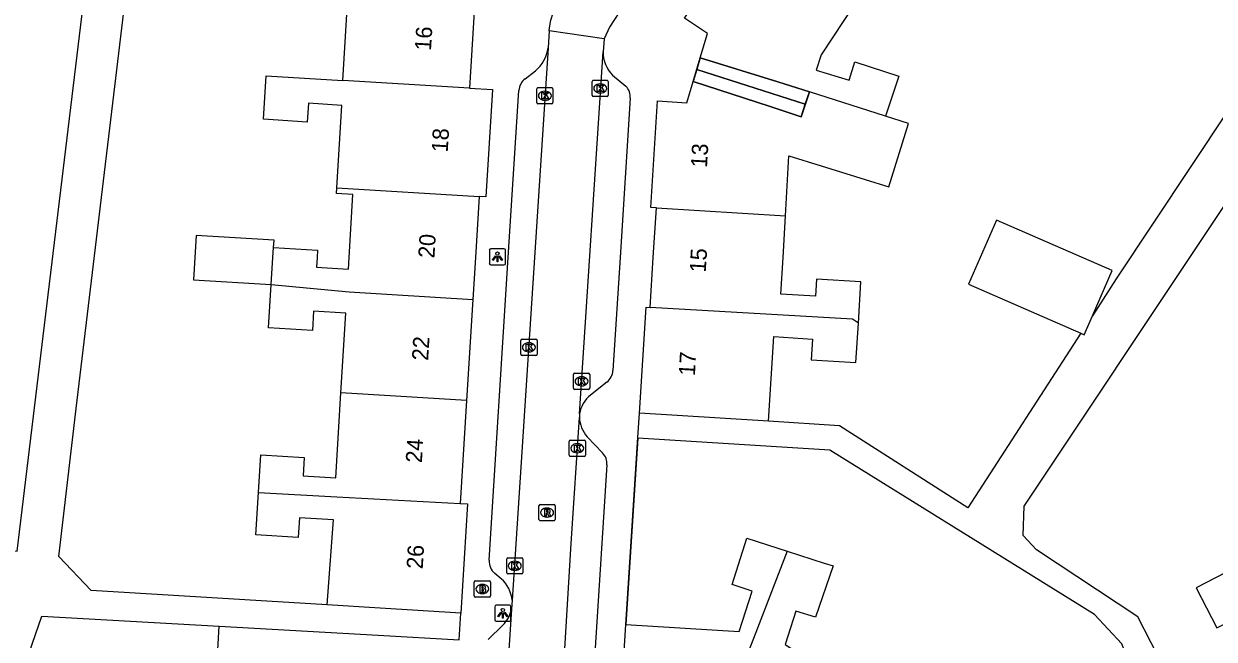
# Model space of a CAD drawing. Extents: x 159280 to 160375, y 384531 to 385872.
# Drawn here: x 160014.7 to 160088.1, y 384726.4 to 384764.4 of the extents above; entities that cross this region are included whole.
import ezdxf

# ---------------------------------------------------------------- set-up
doc = ezdxf.new("R2010")
doc.units = 0
for name, color, linetype in [('IMGEO_Brandkraan', 7, 'Continuous'), ('IMGEO_Kolk', 7, 'Continuous'), ('IMGEO_Lichtpunt', 7, 'Continuous'), ('IMGEO_Muur', 7, 'Continuous'), ('IMGEO_Pand', 7, 'Continuous'), ('IMGEO_Pand_nummerreeks', 7, 'Continuous'), ('IMGEO_Pand_overbouw', 7, 'Continuous'), ('IMGEO_Rijbaan_lokaal_open', 7, 'Continuous'), ('IMGEO_Rioolput', 7, 'Continuous'), ('IMGEO_Voetpad_open', 7, 'Continuous')]:
    doc.layers.add(name, color=color, linetype=linetype)

msp = doc.modelspace()

# ---------------------------------------------------------------- linework, layer by layer
at = {"layer": 'IMGEO_Brandkraan'}
for p, q in [((160042.486, 384729.118), (160042.486, 384729.97)), ((160042.561, 384730.044), (160043.413, 384730.044)), ((160042.974, 384729.824), (160042.999, 384729.824)), ((160043.487, 384729.97), (160043.487, 384729.118)), ((160043.413, 384729.044), (160042.561, 384729.044)), ((160042.997, 384729.264), (160042.972, 384729.264))]:
    msp.add_line(p, q, dxfattribs=at)
for points in [[(160042.486, 384729.118), (160042.486, 384729.97)], [(160042.561, 384730.044), (160043.413, 384730.044)], [(160042.834, 384729.744), (160042.834, 384729.344), (160043.047, 384729.344)], [(160043.065, 384729.744), (160042.834, 384729.744)], [(160043.013, 384729.663), (160042.959, 384729.663), (160042.959, 384729.587)], [(160042.959, 384729.587), (160043.012, 384729.587)], [(160043.021, 384729.511), (160042.959, 384729.511), (160042.959, 384729.43)], [(160042.959, 384729.43), (160043.021, 384729.43)], [(160043.487, 384729.97), (160043.487, 384729.118)], [(160043.413, 384729.044), (160042.561, 384729.044)]]:
    msp.add_lwpolyline(points, dxfattribs=at)
for centre, radius, start, end in [((160042.563, 384729.968), 0.0765, 91.55205, 178.44795), ((160042.563, 384729.968), 0.0765, 91.55205, 178.44795), ((160043.014, 384729.625), 0.0379, 267.82845, 90.93552), ((160043.022, 384729.47), 0.0404, 269.87594, 90.50774), ((160043.069, 384729.599), 0.145, 59.4692, 91.53667), ((160043.094, 384729.646), 0.0922, 285.51372, 58.15012), ((160043.099, 384729.454), 0.105, 301.31148, 78.98903), ((160043.411, 384729.968), 0.0765, 1.55205, 88.44795), ((160043.411, 384729.968), 0.0765, 1.55205, 88.44795), ((160042.563, 384729.12), 0.0765, 181.55205, 268.44795), ((160042.563, 384729.12), 0.0765, 181.55205, 268.44795), ((160043.053, 384729.595), 0.251, 268.66757, 293.53466), ((160043.411, 384729.12), 0.0765, 271.55205, 358.44795), ((160043.411, 384729.12), 0.0765, 271.55205, 358.44795)]:
    msp.add_arc(centre, radius, start, end, dxfattribs=at)
for centre, major_axis, ratio, start_param, end_param in [((160042.973, 384729.544), (-0.387, 0.002), 0.722429, 4.712389, 7.853982), ((160042.998, 384729.544), (-0.39, 0.002), 0.717154, 1.570796, 4.712389)]:
    msp.add_ellipse(centre, major_axis=major_axis, ratio=ratio, start_param=start_param, end_param=end_param, dxfattribs=at)
at = {"layer": 'IMGEO_Kolk'}
for p, q in [((160046.34, 384759.554), (160046.34, 384760.406)), ((160046.415, 384760.48), (160047.267, 384760.48)), ((160046.828, 384760.26), (160046.853, 384760.26)), ((160047.341, 384760.406), (160047.341, 384759.554)), ((160049.754, 384760.006), (160049.754, 384760.858)), ((160049.829, 384760.932), (160050.681, 384760.932)), ((160050.242, 384760.712), (160050.267, 384760.712)), ((160050.755, 384760.858), (160050.755, 384760.006)), ((160046.851, 384759.7), (160046.826, 384759.7)), ((160050.681, 384759.932), (160049.829, 384759.932)), ((160050.265, 384760.152), (160050.24, 384760.152)), ((160047.267, 384759.48), (160046.415, 384759.48)), ((160045.359, 384744.032), (160045.359, 384744.884)), ((160045.434, 384744.958), (160046.286, 384744.958)), ((160046.36, 384744.884), (160046.36, 384744.032)), ((160045.87, 384744.178), (160045.845, 384744.178)), ((160045.847, 384744.738), (160045.872, 384744.738)), ((160046.286, 384743.958), (160045.434, 384743.958)), ((160048.605, 384741.934), (160048.605, 384742.786)), ((160048.68, 384742.86), (160049.532, 384742.86)), ((160049.093, 384742.64), (160049.118, 384742.64)), ((160049.606, 384742.786), (160049.606, 384741.934)), ((160049.116, 384742.08), (160049.091, 384742.08)), ((160049.532, 384741.86), (160048.68, 384741.86)), ((160048.343, 384737.803), (160048.343, 384738.655)), ((160048.418, 384738.729), (160049.27, 384738.729)), ((160048.831, 384738.509), (160048.856, 384738.509)), ((160049.344, 384738.655), (160049.344, 384737.803)), ((160049.27, 384737.729), (160048.418, 384737.729)), ((160048.854, 384737.949), (160048.829, 384737.949)), ((160044.487, 384730.55), (160044.487, 384731.402)), ((160044.562, 384731.476), (160045.414, 384731.476)), ((160044.975, 384731.256), (160045, 384731.256)), ((160045.488, 384731.402), (160045.488, 384730.55)), ((160045.414, 384730.476), (160044.562, 384730.476)), ((160044.998, 384730.696), (160044.973, 384730.696))]:
    msp.add_line(p, q, dxfattribs=at)
for points in [[(160046.34, 384759.554), (160046.34, 384760.406)], [(160046.415, 384760.48), (160047.267, 384760.48)], [(160047.341, 384760.406), (160047.341, 384759.554)], [(160049.754, 384760.006), (160049.754, 384760.858)], [(160049.829, 384760.932), (160050.681, 384760.932)], [(160050.075, 384760.632), (160050.198, 384760.632), (160050.198, 384760.481), (160050.328, 384760.632), (160050.492, 384760.632), (160050.346, 384760.481), (160050.499, 384760.232), (160050.347, 384760.232), (160050.262, 384760.396), (160050.198, 384760.329), (160050.198, 384760.232), (160050.075, 384760.232), (160050.075, 384760.632)], [(160050.755, 384760.858), (160050.755, 384760.006)], [(160046.661, 384760.18), (160046.784, 384760.18), (160046.784, 384760.029), (160046.914, 384760.18), (160047.078, 384760.18), (160046.932, 384760.029), (160047.085, 384759.78), (160046.933, 384759.78), (160046.848, 384759.944), (160046.784, 384759.877), (160046.784, 384759.78), (160046.661, 384759.78), (160046.661, 384760.18)], [(160050.681, 384759.932), (160049.829, 384759.932)], [(160047.267, 384759.48), (160046.415, 384759.48)], [(160045.359, 384744.032), (160045.359, 384744.884)], [(160045.434, 384744.958), (160046.286, 384744.958)], [(160046.36, 384744.884), (160046.36, 384744.032)], [(160045.68, 384744.658), (160045.803, 384744.658), (160045.803, 384744.507), (160045.933, 384744.658), (160046.097, 384744.658), (160045.951, 384744.507), (160046.104, 384744.258), (160045.952, 384744.258), (160045.867, 384744.422), (160045.803, 384744.355), (160045.803, 384744.258), (160045.68, 384744.258), (160045.68, 384744.658)], [(160046.286, 384743.958), (160045.434, 384743.958)], [(160048.605, 384741.934), (160048.605, 384742.786)], [(160048.68, 384742.86), (160049.532, 384742.86)], [(160049.606, 384742.786), (160049.606, 384741.934)], [(160048.926, 384742.56), (160049.049, 384742.56), (160049.049, 384742.409), (160049.179, 384742.56), (160049.343, 384742.56), (160049.197, 384742.409), (160049.35, 384742.16), (160049.198, 384742.16), (160049.113, 384742.324), (160049.049, 384742.257), (160049.049, 384742.16), (160048.926, 384742.16), (160048.926, 384742.56)], [(160049.532, 384741.86), (160048.68, 384741.86)], [(160048.343, 384737.803), (160048.343, 384738.655)], [(160048.418, 384738.729), (160049.27, 384738.729)], [(160048.664, 384738.429), (160048.787, 384738.429), (160048.787, 384738.278), (160048.917, 384738.429), (160049.081, 384738.429), (160048.935, 384738.278), (160049.088, 384738.029), (160048.936, 384738.029), (160048.851, 384738.193), (160048.787, 384738.126), (160048.787, 384738.029), (160048.664, 384738.029), (160048.664, 384738.429)], [(160049.344, 384738.655), (160049.344, 384737.803)], [(160049.27, 384737.729), (160048.418, 384737.729)], [(160044.487, 384730.55), (160044.487, 384731.402)], [(160044.562, 384731.476), (160045.414, 384731.476)], [(160044.808, 384731.176), (160044.931, 384731.176), (160044.931, 384731.025), (160045.061, 384731.176), (160045.225, 384731.176), (160045.079, 384731.025), (160045.232, 384730.776), (160045.08, 384730.776), (160044.995, 384730.94), (160044.931, 384730.873), (160044.931, 384730.776), (160044.808, 384730.776), (160044.808, 384731.176)], [(160045.488, 384731.402), (160045.488, 384730.55)], [(160045.414, 384730.476), (160044.562, 384730.476)]]:
    msp.add_lwpolyline(points, dxfattribs=at)
for centre, start, end in [((160046.417, 384760.404), 91.55205, 178.44795), ((160046.417, 384760.404), 91.55205, 178.44795), ((160047.265, 384760.404), 1.55205, 88.44795), ((160047.265, 384760.404), 1.55205, 88.44795), ((160049.831, 384760.856), 91.55205, 178.44795), ((160049.831, 384760.856), 91.55205, 178.44795), ((160050.679, 384760.856), 1.55205, 88.44795), ((160050.679, 384760.856), 1.55205, 88.44795), ((160046.417, 384759.556), 181.55205, 268.44795), ((160046.417, 384759.556), 181.55205, 268.44795), ((160047.265, 384759.556), 271.55205, 358.44795), ((160047.265, 384759.556), 271.55205, 358.44795), ((160049.831, 384760.008), 181.55205, 268.44795), ((160049.831, 384760.008), 181.55205, 268.44795), ((160050.679, 384760.008), 271.55205, 358.44795), ((160050.679, 384760.008), 271.55205, 358.44795), ((160045.436, 384744.882), 91.55205, 178.44795), ((160045.436, 384744.882), 91.55205, 178.44795), ((160046.284, 384744.882), 1.55205, 88.44795), ((160046.284, 384744.882), 1.55205, 88.44795), ((160045.436, 384744.034), 181.55205, 268.44795), ((160045.436, 384744.034), 181.55205, 268.44795), ((160046.284, 384744.034), 271.55205, 358.44795), ((160046.284, 384744.034), 271.55205, 358.44795), ((160048.682, 384742.784), 91.55205, 178.44795), ((160048.682, 384742.784), 91.55205, 178.44795), ((160049.53, 384742.784), 1.55205, 88.44795), ((160049.53, 384742.784), 1.55205, 88.44795), ((160048.682, 384741.936), 181.55205, 268.44795), ((160048.682, 384741.936), 181.55205, 268.44795), ((160049.53, 384741.936), 271.55205, 358.44795), ((160049.53, 384741.936), 271.55205, 358.44795), ((160048.42, 384738.653), 91.55205, 178.44795), ((160048.42, 384738.653), 91.55205, 178.44795), ((160049.268, 384738.653), 1.55205, 88.44795), ((160049.268, 384738.653), 1.55205, 88.44795), ((160048.42, 384737.805), 181.55205, 268.44795), ((160048.42, 384737.805), 181.55205, 268.44795), ((160049.268, 384737.805), 271.55205, 358.44795), ((160049.268, 384737.805), 271.55205, 358.44795), ((160044.564, 384731.4), 91.55205, 178.44795), ((160044.564, 384731.4), 91.55205, 178.44795), ((160045.412, 384731.4), 1.55205, 88.44795), ((160045.412, 384731.4), 1.55205, 88.44795), ((160044.564, 384730.552), 181.55205, 268.44795), ((160044.564, 384730.552), 181.55205, 268.44795), ((160045.412, 384730.552), 271.55205, 358.44795), ((160045.412, 384730.552), 271.55205, 358.44795)]:
    msp.add_arc(centre, 0.0765, start, end, dxfattribs=at)
for centre, major_axis, ratio, start_param, end_param in [((160046.827, 384759.98), (-0.387, 0.002), 0.722429, 4.712389, 7.853982), ((160046.852, 384759.98), (-0.39, 0.002), 0.717154, 1.570796, 4.712389), ((160050.241, 384760.432), (-0.387, 0.002), 0.722429, 4.712389, 7.853982), ((160050.266, 384760.432), (-0.39, 0.002), 0.717154, 1.570796, 4.712389), ((160045.846, 384744.458), (-0.387, 0.002), 0.722429, 4.712389, 7.853982), ((160045.871, 384744.458), (-0.39, 0.002), 0.717154, 1.570796, 4.712389), ((160049.092, 384742.36), (-0.387, 0.002), 0.722429, 4.712389, 7.853982), ((160049.117, 384742.36), (-0.39, 0.002), 0.717154, 1.570796, 4.712389), ((160048.83, 384738.229), (-0.387, 0.002), 0.722429, 4.712389, 7.853982), ((160048.855, 384738.229), (-0.39, 0.002), 0.717154, 1.570796, 4.712389), ((160044.974, 384730.976), (-0.387, 0.002), 0.722429, 4.712389, 7.853982), ((160044.999, 384730.976), (-0.39, 0.002), 0.717154, 1.570796, 4.712389)]:
    msp.add_ellipse(centre, major_axis=major_axis, ratio=ratio, start_param=start_param, end_param=end_param, dxfattribs=at)
at = {"layer": 'IMGEO_Lichtpunt'}
for p, q in [((160043.418, 384750.444), (160043.418, 384749.637)), ((160043.418, 384750.444), (160043.418, 384749.637)), ((160044.32, 384750.539), (160043.512, 384750.539)), ((160044.32, 384750.539), (160043.512, 384750.539)), ((160044.414, 384749.637), (160044.414, 384750.444)), ((160044.414, 384749.637), (160044.414, 384750.444)), ((160043.512, 384749.543), (160044.32, 384749.543)), ((160043.512, 384749.543), (160044.32, 384749.543)), ((160043.754, 384728.45), (160043.754, 384727.643)), ((160043.754, 384728.45), (160043.754, 384727.643)), ((160044.656, 384728.545), (160043.848, 384728.545)), ((160044.656, 384728.545), (160043.848, 384728.545)), ((160044.75, 384727.643), (160044.75, 384728.45)), ((160044.75, 384727.643), (160044.75, 384728.45)), ((160043.848, 384727.549), (160044.656, 384727.549)), ((160043.848, 384727.549), (160044.656, 384727.549))]:
    msp.add_line(p, q, dxfattribs=at)
for points in [[(160043.792, 384750.108), (160043.831, 384750.08), (160043.643, 384749.818), (160043.605, 384749.845), (160043.792, 384750.108)], [(160043.894, 384750.06), (160043.941, 384750.06), (160043.941, 384749.738), (160043.894, 384749.738), (160043.894, 384750.06)], [(160044.004, 384750.08), (160044.042, 384750.107), (160044.229, 384749.845), (160044.19, 384749.817), (160044.004, 384750.08)], [(160044.128, 384728.114), (160044.167, 384728.086), (160043.979, 384727.824), (160043.941, 384727.851), (160044.128, 384728.114)], [(160044.23, 384728.066), (160044.277, 384728.066), (160044.277, 384727.744), (160044.23, 384727.744), (160044.23, 384728.066)], [(160044.34, 384728.086), (160044.378, 384728.113), (160044.565, 384727.851), (160044.526, 384727.823), (160044.34, 384728.086)]]:
    msp.add_lwpolyline(points, dxfattribs=at)
for centre in [(160043.917, 384750.242), (160044.253, 384728.248)]:
    msp.add_circle(centre, 0.0994, dxfattribs=at)
for centre, start, end in [((160043.512, 384750.444), 90, 180), ((160043.512, 384750.444), 90, 180), ((160044.32, 384750.444), 0, 90), ((160044.32, 384750.444), 0, 90), ((160043.512, 384749.637), 180, 270), ((160043.512, 384749.637), 180, 270), ((160044.32, 384749.637), 270, 0), ((160044.32, 384749.637), 270, 360), ((160043.848, 384728.45), 90, 180), ((160043.848, 384728.45), 90, 180), ((160044.656, 384728.45), 0, 90), ((160044.656, 384728.45), 0, 90), ((160043.848, 384727.643), 180, 270), ((160043.848, 384727.643), 180, 270), ((160044.656, 384727.643), 270, 0), ((160044.656, 384727.643), 270, 360)]:
    msp.add_arc(centre, 0.0946, start, end, dxfattribs=at)
at = {"layer": 'IMGEO_Muur'}
msp.add_lwpolyline([(160051.838, 384727.361), (160052.578, 384738.89)], dxfattribs=at)
at = {"layer": 'IMGEO_Pand'}
for points in [[(160034.384, 384760.923), (160034.78, 384767.393), (160032.683, 384768.135), (160032.319, 384766.974), (160029.657, 384767.772), (160030.296, 384769.918)], [(160056.43, 384762.314), (160056.88, 384763.817), (160055.458, 384764.761), (160059.135, 384770.303), (160059.437, 384770.102)], [(160042.553, 384766.197), (160042.2, 384760.442)], [(160065.958, 384765.643), (160063.874, 384762.502), (160063.57, 384761.554), (160065.601, 384760.943), (160065.966, 384762.073), (160068.678, 384761.186), (160067.849, 384758.715)], [(160056.43, 384762.314), (160061.205, 384760.83), (160063.156, 384760.223)], [(160034.01, 384754.297), (160034.322, 384759.387), (160032.256, 384759.513), (160032.185, 384758.36), (160029.483, 384758.525), (160029.648, 384761.215), (160034.384, 384760.923)], [(160042.2, 384760.442), (160034.384, 384760.923)], [(160042.2, 384760.442), (160043.61, 384760.356), (160043.205, 384753.733), (160042.786, 384753.758)], [(160053.724, 384753.069), (160053.385, 384753.092), (160053.795, 384759.662), (160055.601, 384759.55), (160055.995, 384760.866)], [(160063.156, 384760.223), (160062.653, 384758.682), (160060.746, 384759.308), (160055.995, 384760.866)], [(160067.849, 384758.715), (160063.156, 384760.223)], [(160061.681, 384752.573), (160061.896, 384756.264), (160063.875, 384755.649), (160066.597, 384754.822), (160068.058, 384754.368), (160069.272, 384758.273), (160067.849, 384758.715)], [(160030.11, 384750.616), (160032.83, 384750.45), (160032.802, 384750), (160032.765, 384749.393), (160034.724, 384749.273), (160034.768, 384750), (160035.006, 384753.892), (160033.989, 384753.954), (160034.01, 384754.297)], [(160034.01, 384754.297), (160042.786, 384753.758)], [(160042.786, 384753.758), (160042.556, 384750), (160042.397, 384747.403)], [(160053.339, 384746.908), (160053.532, 384750), (160053.724, 384753.069)], [(160053.724, 384753.069), (160061.681, 384752.573)], [(160066.177, 384745.957), (160066.335, 384748.489), (160063.591, 384748.66), (160063.526, 384747.608), (160061.399, 384747.741), (160061.531, 384750), (160061.681, 384752.573)], [(160080.608, 384746.402), (160081.826, 384749.194), (160074.698, 384752.305), (160072.971, 384748.347), (160079.906, 384745.32)], [(160030.11, 384750.616), (160030.137, 384751.062), (160025.344, 384751.355), (160025.177, 384748.624), (160029.97, 384748.331)], [(160029.97, 384748.331), (160030.072, 384750), (160030.11, 384750.616)], [(160034.267, 384741.64), (160034.569, 384746.57), (160032.582, 384746.692), (160032.509, 384745.485), (160029.806, 384745.651), (160029.97, 384748.331)], [(160029.97, 384748.331), (160034.763, 384747.871), (160042.397, 384747.403)], [(160042.397, 384747.403), (160042.015, 384741.166)], [(160052.673, 384740.386), (160053.08, 384746.924), (160053.339, 384746.908)], [(160066.177, 384745.957), (160065.821, 384746.19), (160053.339, 384746.908)], [(160079.906, 384745.32), (160080.099, 384745.236), (160080.608, 384746.402)], [(160060.631, 384739.89), (160060.957, 384745.119), (160063.352, 384744.969), (160063.271, 384743.683), (160066.025, 384743.512), (160066.177, 384745.957)], [(160029.182, 384735.499), (160029.325, 384737.831), (160032.004, 384737.667), (160031.934, 384736.534), (160033.947, 384736.411), (160034.267, 384741.64)], [(160042.015, 384741.166), (160034.267, 384741.64)], [(160042.015, 384741.166), (160041.626, 384734.817)], [(160060.631, 384739.89), (160057.664, 384740.075), (160052.673, 384740.386)], [(160033.408, 384728.567), (160033.804, 384733.815), (160031.704, 384733.943), (160031.629, 384732.73), (160029.023, 384732.889), (160029.182, 384735.499)], [(160029.182, 384735.499), (160034.002, 384735.234), (160041.626, 384734.817)], [(160041.626, 384734.817), (160042.078, 384734.789), (160041.666, 384728.061)], [(160051.838, 384727.361), (160058.825, 384726.924), (160059.625, 384729.419), (160058.388, 384729.816), (160059.305, 384732.673), (160061.789, 384731.877)], [(160061.789, 384731.877), (160059.844, 384726.862), (160056.873, 384719.2)], [(160061.789, 384731.877), (160064.067, 384731.146), (160064.614, 384730.971), (160063.537, 384727.798), (160062.327, 384728.173), (160061.67, 384726.115), (160067.165, 384722.466)], [(160089.437, 384730.863), (160087.011, 384729.616), (160088.283, 384727.141), (160089.38, 384727.705), (160090.495, 384725.534), (160085.828, 384723.135)], [(160041.666, 384728.061), (160036.676, 384728.367), (160033.408, 384728.567)], [(160031.594, 384720.394), (160031.608, 384720.638), (160031.875, 384725.365), (160029.752, 384725.485), (160029.678, 384724.184), (160026.597, 384724.358), (160026.76, 384727.243)], [(160026.76, 384727.243), (160036.563, 384726.689), (160041.555, 384726.407)], [(160051.315, 384719.018), (160051.838, 384727.361)]]:
    msp.add_lwpolyline(points, dxfattribs=at)
at = {"layer": 'IMGEO_Pand_overbouw'}
for points in [[(160062.905, 384759.453), (160063.156, 384760.223), (160061.205, 384760.83), (160056.43, 384762.314), (160056.213, 384761.59)], [(160055.995, 384760.866), (160060.746, 384759.308), (160062.653, 384758.682), (160062.905, 384759.453), (160056.213, 384761.59)]]:
    msp.add_lwpolyline(points, close=True, dxfattribs=at)
at = {"layer": 'IMGEO_Rijbaan_lokaal_open'}
for points in [[(160047.104, 384763.984), (160047.129, 384764.178), (160047.22, 384764.64), (160047.352, 384765.092), (160047.523, 384765.53), (160047.733, 384765.952), (160050.513, 384770.167)], [(160053.48, 384768.295), (160050.819, 384764.211), (160050.493, 384763.486)], [(160047.104, 384763.984), (160047.045, 384762.935)], [(160050.493, 384763.486), (160047.104, 384763.984)], [(160050.493, 384763.486), (160050.434, 384762.69)], [(160047.045, 384762.935), (160044.822, 384728.85)], [(160048.987, 384740.357), (160050.434, 384762.69)], [(160047.342, 384713.529), (160048.469, 384732.359), (160048.973, 384740.135)], [(160048.987, 384740.357), (160048.973, 384740.135)], [(160044.822, 384728.85), (160044.785, 384728.292)], [(160044.785, 384728.292), (160043.761, 384712.594)]]:
    msp.add_lwpolyline(points, dxfattribs=at)
at = {"layer": 'IMGEO_Rioolput'}
for p, q in [((160046.48, 384733.833), (160046.48, 384734.685)), ((160046.555, 384734.759), (160047.407, 384734.759)), ((160046.968, 384734.539), (160046.993, 384734.539)), ((160047.481, 384734.685), (160047.481, 384733.833)), ((160046.991, 384733.979), (160046.966, 384733.979)), ((160047.407, 384733.759), (160046.555, 384733.759))]:
    msp.add_line(p, q, dxfattribs=at)
for points in [[(160046.48, 384733.833), (160046.48, 384734.685)], [(160046.555, 384734.759), (160047.407, 384734.759)], [(160047.481, 384734.685), (160047.481, 384733.833)], [(160047.069, 384734.457), (160046.817, 384734.459), (160046.817, 384734.059)], [(160046.817, 384734.059), (160046.941, 384734.059), (160046.941, 384734.221), (160046.952, 384734.221)], [(160046.995, 384734.378), (160046.941, 384734.378), (160046.941, 384734.297)], [(160046.941, 384734.297), (160046.993, 384734.297)], [(160046.999, 384734.192), (160047.07, 384734.059), (160047.21, 384734.059), (160047.145, 384734.185)], [(160047.407, 384733.759), (160046.555, 384733.759)]]:
    msp.add_lwpolyline(points, dxfattribs=at)
for centre, radius, start, end in [((160046.557, 384734.683), 0.0765, 91.55205, 178.44795), ((160046.557, 384734.683), 0.0765, 91.55205, 178.44795), ((160047.405, 384734.683), 0.0765, 1.55205, 88.44795), ((160047.405, 384734.683), 0.0765, 1.55205, 88.44795), ((160046.557, 384733.835), 0.0765, 181.55205, 268.44795), ((160046.557, 384733.835), 0.0765, 181.55205, 268.44795), ((160046.951, 384734.168), 0.0533, 26.02933, 88.69889), ((160046.977, 384734.486), 0.19, 274.7715, 282.96867), ((160047.001, 384734.282), 0.0964, 77.00612, 93.18647), ((160047.015, 384734.339), 0.0378, 276.66336, 79.67722), ((160047.068, 384734.347), 0.109, 350.36119, 89.41601), ((160047.066, 384734.347), 0.112, 277.58423, 350.98172), ((160047.05, 384734.132), 0.108, 29.51342, 73.79051), ((160047.405, 384733.835), 0.0765, 271.55205, 358.44795), ((160047.405, 384733.835), 0.0765, 271.55205, 358.44795)]:
    msp.add_arc(centre, radius, start, end, dxfattribs=at)
for centre, major_axis, ratio, start_param, end_param in [((160046.967, 384734.259), (-0.387, 0.002), 0.722429, 4.712389, 7.853982), ((160046.992, 384734.259), (-0.39, 0.002), 0.717154, 1.570796, 4.712389)]:
    msp.add_ellipse(centre, major_axis=major_axis, ratio=ratio, start_param=start_param, end_param=end_param, dxfattribs=at)
at = {"layer": 'IMGEO_Voetpad_open'}
for points in [[(159986.258, 384735.984), (160003.921, 384733.4), (160014.299, 384731.886), (160015.76, 384743.962), (160020.308, 384781.549), (160021.355, 384784.522), (160035.962, 384806.663), (160044.571, 384819.713), (160029.19, 384829.86)], [(160083.386, 384792.633), (160102.732, 384779.798), (160082.082, 384748.674), (160080.608, 384746.402)], [(160033.408, 384728.567), (160018.853, 384729.458), (160016.873, 384731.545), (160017.93, 384740.679), (160022.838, 384781.473), (160023.505, 384783.333), (160028.705, 384790.452)], [(160085.828, 384723.135), (160083.411, 384727.836), (160077.168, 384731.965), (160076.338, 384732.838), (160076.406, 384734.653), (160077.516, 384736.321), (160104.922, 384777.509), (160107.372, 384778.093), (160125.781, 384765.927)], [(160055.995, 384760.866), (160056.43, 384762.314)], [(160045.625, 384761.025), (160046.255, 384761.51)], [(160051.011, 384761.259), (160051.843, 384760.567)], [(160043.406, 384731.32), (160044.586, 384750), (160045.237, 384760.296)], [(160052.108, 384759.824), (160051.484, 384750), (160051.041, 384743.028)], [(160079.906, 384745.32), (160072.921, 384734.556), (160065.021, 384739.616), (160060.631, 384739.89)], [(160050.664, 384742.307), (160049.653, 384741.505)], [(160052.576, 384738.857), (160052.578, 384738.89), (160052.673, 384740.386)], [(160049.461, 384738.939), (160050.399, 384737.947)], [(160052.576, 384738.857), (160051.838, 384727.361)], [(160082.579, 384725.791), (160082.417, 384726.151), (160080.742, 384727.961), (160064.414, 384738.105), (160052.576, 384738.857)], [(160050.671, 384737.196), (160049.523, 384719.116), (160049.356, 384716.481)], [(160044.141, 384730.171), (160043.76, 384730.492)], [(160041.555, 384726.407), (160041.666, 384728.061)], [(160002.494, 384686.271), (160003.116, 384691.117), (160015.824, 384727.861), (160026.76, 384727.243)], [(160044.252, 384727.319), (160043.353, 384726.435)]]:
    msp.add_lwpolyline(points, dxfattribs=at)
for centre, radius, start, end in [((160044.835, 384763.229), 2.229, 309.56082, 352.43244), ((160052.37, 384762.639), 1.936, 178.48139, 225.43863), ((160046.234, 384760.233), 0.998, 127.54916, 176.40382), ((160051.117, 384759.889), 0.993, 356.22237, 43.03642), ((160050.033, 384743.096), 1.01, 308.64046, 356.15077), ((160050.794, 384740.076), 1.829, 128.6077, 171.15288), ((160050.798, 384740.182), 1.826, 181.47849, 222.91506), ((160049.675, 384737.26), 0.998, 356.3225, 43.49663), ((160044.403, 384731.256), 0.999, 176.34654, 229.95038), ((160042.897, 384728.694), 1.931, 4.64388, 49.90001), ((160042.894, 384728.696), 1.934, 314.61929, 347.95371)]:
    msp.add_arc(centre, radius, start, end, dxfattribs=at)

# ---------------------------------------------------------------- texts
at = {"layer": 'IMGEO_Pand_nummerreeks'}
for s, rotation, p in [('16', 86.48999, (160039.816, 384762.739)), ('18', 86.50069, (160040.848, 384756.467)), ('13', 86.66874, (160056.84, 384755.524)), ('20', 86.49598, (160040.027, 384749.936)), ('15', 86.4254, (160056.761, 384749.053)), ('22', 86.49598, (160039.64, 384743.615)), ('17', 86.66874, (160056.092, 384742.673)), ('24', 86.49598, (160039.254, 384737.304)), ('26', 86.49577, (160039.306, 384730.754))]:
    msp.add_text(s, height=1, rotation=rotation, dxfattribs=at).set_placement(p)

doc.saveas('drawing.dxf')
